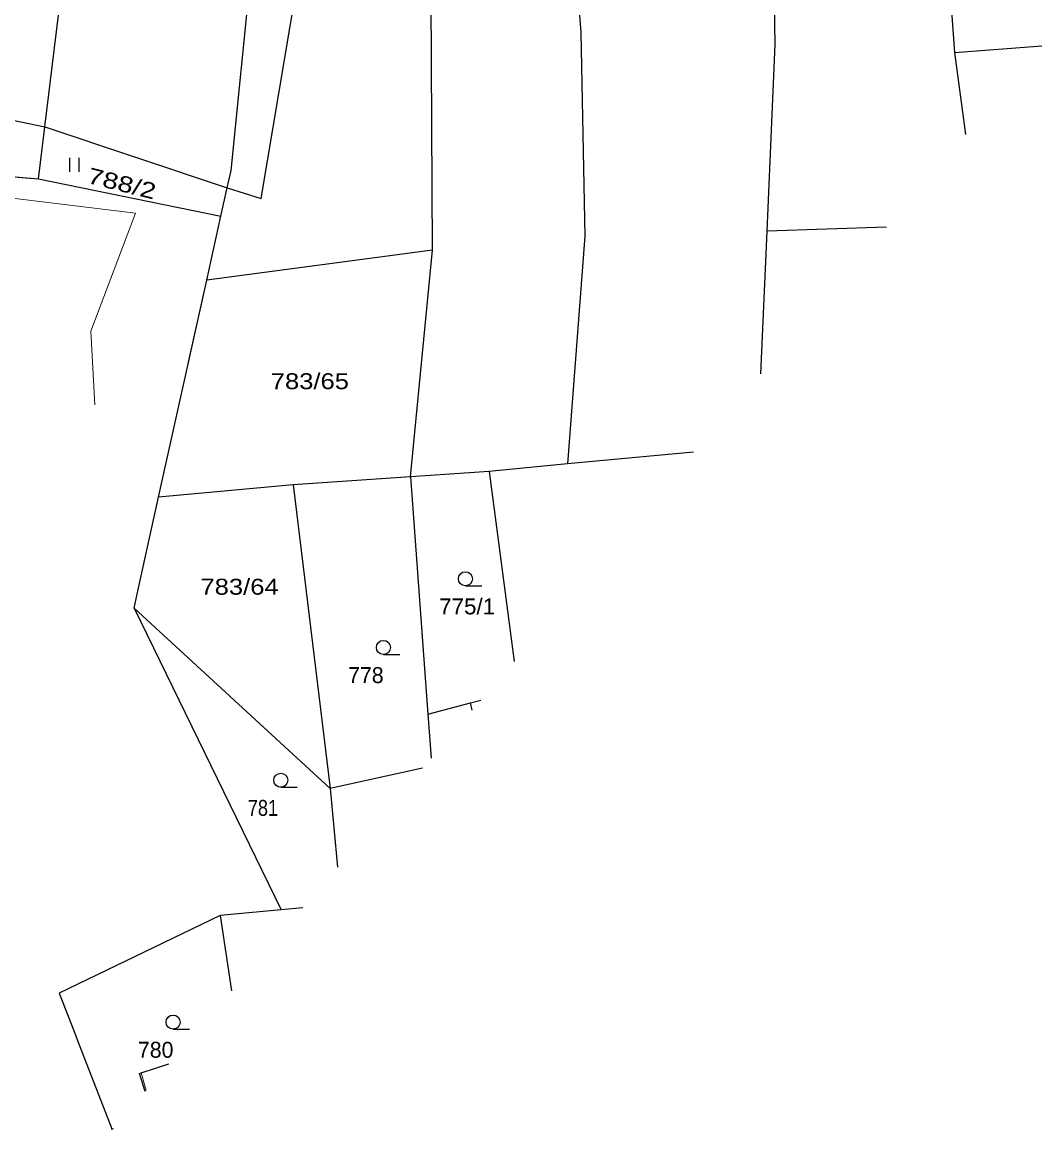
# Model space of a CAD drawing. Extents: x -546984 to -546090, y -1194931 to -1194069.
# Drawn here: x -546588.4 to -546479.6, y -1194872.4 to -1194754.2 of the extents above; entities that cross this region are included whole.
import ezdxf
from ezdxf.enums import TextEntityAlignment as Align

# ---------------------------------------------------------------- set-up
doc = ezdxf.new("R2010")
doc.units = 0
doc.header["$LTSCALE"] = 0.68
for name, color, linetype, lineweight in [('1', 7, 'Continuous', 25), ('3', 7, 'Continuous', 25), ('4', 7, 'Continuous', 13)]:
    doc.layers.add(name, color=color, linetype=linetype, lineweight=lineweight)
doc.layers.add('2', color=7, linetype='Continuous')

msp = doc.modelspace()

# ---------------------------------------------------------------- linework, layer by layer
at = {"layer": '1'}
for p, q in [((-546488.9, -1194757.45), (-546493.69, -1194687.04)), ((-546623.54, -1194767.75), (-546586.67, -1194770.93)), ((-546586.67, -1194770.93), (-546567.2, -1194774.9)), ((-546567.2, -1194774.9), (-546566.53, -1194771.87)), ((-546568.71, -1194781.71), (-546567.2, -1194774.9)), ((-546568.71, -1194781.71), (-546567.2, -1194774.9)), ((-546509.607, -1194791.711), (-546508.91, -1194776.49)), ((-546496.185, -1194776.065), (-546508.91, -1194776.49)), ((-546544.63, -1194778.53), (-546568.71, -1194781.71)), ((-546546.96, -1194802.69), (-546544.63, -1194778.53)), ((-546570.654, -1194790.481), (-546568.71, -1194781.71)), ((-546546.96, -1194802.69), (-546559.48, -1194803.57)), ((-546559.48, -1194803.57), (-546573.84, -1194804.86)), ((-546559.48, -1194803.57), (-546555.54, -1194835.93)), ((-546540.57, -1194826.8), (-546539.455, -1194826.504)), ((-546540.389, -1194827.592), (-546540.57, -1194826.8)), ((-546545.11, -1194828), (-546544.764, -1194832.693)), ((-546567.26, -1194849.5), (-546584.46, -1194857.77)), ((-546578.83, -1194872.26), (-546578.66, -1194872.204)), ((-546578.785, -1194872.351), (-546578.83, -1194872.26))]:
    msp.add_line(p, q, dxfattribs=at)
for points in [[(-546566.53, -1194771.87), (-546562.89, -1194773), (-546552.83, -1194713.17), (-546551.06, -1194684.9), (-546568.37, -1194654.58)], [(-546566.53, -1194771.87), (-546566.11, -1194770.01), (-546560.65, -1194715.77), (-546554.01, -1194686.01), (-546569.74, -1194656.25)], [(-546508.91, -1194776.49), (-546508.05, -1194756.59), (-546508.87, -1194708.28), (-546511.54, -1194674.34)], [(-546585.99, -1194765.36), (-546576.27, -1194686.01), (-546587.01, -1194676.23)], [(-546523.48, -1194677.44), (-546521.76, -1194696.57), (-546528.48, -1194729.44), (-546529.66, -1194744.16), (-546528.8, -1194755.3), (-546528.37, -1194777.02), (-546530.23, -1194801.33)], [(-546544.63, -1194778.53), (-546544.76, -1194751.68), (-546543.9, -1194738.48), (-546540.57, -1194720.86), (-546536.58, -1194704.19), (-546537.9, -1194681.47)], [(-546682.73, -1194756.38), (-546658.62, -1194766.93), (-546638.65, -1194766.81), (-546623.54, -1194767.75), (-546586.67, -1194770.93), (-546567.2, -1194774.9)], [(-546487.723, -1194766.201), (-546488.9, -1194757.45), (-546479.606, -1194756.739)], [(-546623.54, -1194767.75), (-546622.76, -1194762.81), (-546622.04, -1194757.86), (-546585.99, -1194765.36)], [(-546586.67, -1194770.93), (-546586.06, -1194765.96), (-546585.99, -1194765.36), (-546566.53, -1194771.87)], [(-546576.47, -1194816.72), (-546576.02, -1194814.71), (-546573.84, -1194804.86), (-546568.71, -1194781.71)], [(-546516.772, -1194800.063), (-546530.23, -1194801.33), (-546538.58, -1194802.12), (-546535.923, -1194822.387)], [(-546538.58, -1194802.12), (-546546.96, -1194802.69), (-546545.11, -1194828), (-546540.57, -1194826.8)], [(-546555.54, -1194835.93), (-546576.47, -1194816.72), (-546560.76, -1194848.88)], [(-546545.694, -1194833.777), (-546555.54, -1194835.93), (-546554.747, -1194844.329)], [(-546558.463, -1194848.661), (-546560.76, -1194848.88), (-546567.26, -1194849.5), (-546566.06, -1194857.517)], [(-546584.46, -1194857.77), (-546582.87, -1194861.87), (-546582.5, -1194862.81), (-546578.83, -1194872.26)], [(-546575.264, -1194868.247), (-546575.89, -1194866.34), (-546575.71, -1194866.28), (-546572.749, -1194865.314)]]:
    msp.add_lwpolyline(points, dxfattribs=at)
at = {"layer": '3'}
for p, q in [((-546583.321, -1194770.16), (-546583.321, -1194768.66)), ((-546582.32, -1194770.16), (-546582.32, -1194768.66)), ((-546541.113, -1194814.32), (-546539.363, -1194814.32)), ((-546549.863, -1194821.65), (-546548.113, -1194821.65)), ((-546560.813, -1194835.81), (-546559.063, -1194835.81)), ((-546572.303, -1194861.61), (-546570.553, -1194861.61))]:
    msp.add_line(p, q, dxfattribs=at)
for centre in [(-546541.1129, -1194813.5698), (-546549.8629, -1194820.8998), (-546560.8129, -1194835.0598), (-546572.3029, -1194860.8598)]:
    msp.add_circle(centre, 0.75, dxfattribs=at)
at = {"layer": '4'}
msp.add_line((-546575.179, -1194868.147), (-546575.71, -1194866.28), dxfattribs=at)
msp.add_lwpolyline([(-546622.46, -1194768.95), (-546576.31, -1194774.57), (-546581.06, -1194787.16), (-546580.633, -1194795.011)], dxfattribs=at)

# ---------------------------------------------------------------- texts
at = {"layer": '2', "width": 1.3}
msp.add_text('788/2', height=1.7, rotation=346, dxfattribs=at).set_placement((-546581.555, -1194771.334))
at = {"layer": '2'}
for s, width, p in [('783/65', 1.2, (-546561.88, -1194793.35)), ('783/64', 1.2, (-546569.38, -1194815.27)), ('775/1', 1.05, (-546543.91, -1194817.37))]:
    msp.add_text(s, height=1.7, dxfattribs=dict(at, width=width)).set_placement(p)
for s, p in [('778', (-546551.73, -1194824.7)), ('780', (-546574.157, -1194864.66))]:
    msp.add_text(s, height=1.7, dxfattribs=at).set_placement(p, align=Align.CENTER)
at = {"layer": '2', "width": 0.85}
msp.add_text('781', height=1.7, dxfattribs=at).set_placement((-546562.7115, -1194838.86), align=Align.CENTER)

doc.saveas('drawing.dxf')
